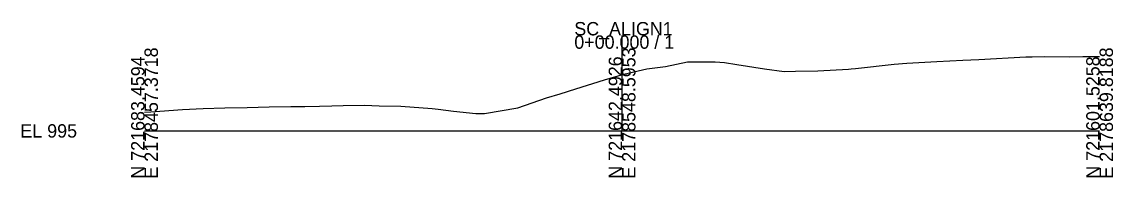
# Model space of a CAD drawing. Extents: x -2342 to 14913, y -10 to 5257.
# Drawn here: x -25.7 to 202.8, y -9.7 to 22.8 of the extents above; entities that cross this region are included whole.
import ezdxf

# ---------------------------------------------------------------- set-up
doc = ezdxf.new("R2010")
doc.units = 0
for name, color, linetype in [('Default', 7, 'Continuous'), ('GK_Cells', 7, 'Continuous'), ('SC_Scratch1', 7, 'Continuous'), ('XS_X_Ground_Line', 7, 'Continuous')]:
    doc.layers.add(name, color=color, linetype=linetype)

msp = doc.modelspace()

# ---------------------------------------------------------------- linework, layer by layer
at = {"layer": 'GK_Cells'}
for p, q in [((100, 0), (100, 20)), ((0, 0), (100, 0)), ((100, 0), (200, 0))]:
    msp.add_line(p, q, dxfattribs=at)
at = {"layer": 'SC_Scratch1'}
msp.add_lwpolyline([(0, 3.9), (1.29, 3.98), (7.94, 4.49), (12.26, 4.72), (16.82, 4.85), (21.48, 4.92), (26.12, 5.02), (30.63, 5.08), (33.56, 5.13), (36.67, 5.18), (39.22, 5.28), (41.63, 5.3), (46.04, 5.37), (49.13, 5.24), (53.67, 5.16), (60.2, 4.66), (61.47, 4.52), (64.72, 4.16), (69.38, 3.62), (71.21, 3.63), (78.15, 4.85), (84.21, 6.92), (87.06, 7.76), (90.29, 8.78), (96.3, 10.68), (100.4, 11.86), (105.2, 12.97), (109.11, 13.48), (113.68, 14.46), (119.49, 14.48), (121.44, 14.33), (124.03, 13.91), (129.8, 12.97), (133.95, 12.43), (136.35, 12.54), (140.96, 12.56), (147.44, 12.93), (147.97, 12.97), (148.87, 13.07), (156.96, 13.97), (159.6, 14.19), (165.93, 14.53), (171.37, 14.81), (174.71, 14.94), (184.56, 15.49), (185.9, 15.52), (188.54, 15.58), (193.64, 15.51), (196.5, 15.6), (200, 15.61)], dxfattribs=at)
at = {"layer": 'XS_X_Ground_Line'}
msp.add_lwpolyline([(0, 3.9), (1.29, 3.98), (7.94, 4.49), (12.26, 4.72), (16.82, 4.85), (21.48, 4.92), (26.12, 5.02), (30.63, 5.08), (33.56, 5.13), (36.67, 5.18), (39.22, 5.28), (41.63, 5.3), (46.04, 5.37), (49.13, 5.24), (53.67, 5.16), (60.2, 4.66), (61.47, 4.52), (64.72, 4.16), (69.38, 3.62), (71.21, 3.63), (78.15, 4.85), (84.21, 6.92), (87.06, 7.76), (90.29, 8.78), (96.3, 10.68), (100.4, 11.86), (105.2, 12.97), (109.11, 13.48), (113.68, 14.46), (119.49, 14.48), (121.44, 14.33), (124.03, 13.91), (129.8, 12.97), (133.95, 12.43), (136.35, 12.54), (140.96, 12.56), (147.44, 12.93), (147.97, 12.97), (148.87, 13.07), (156.96, 13.97), (159.6, 14.19), (165.93, 14.53), (171.37, 14.81), (174.71, 14.94), (184.56, 15.49), (185.9, 15.52), (188.54, 15.58), (193.64, 15.51), (196.5, 15.6), (200, 15.61)], dxfattribs=at)

# ---------------------------------------------------------------- texts
at = {"layer": 'Default'}
msp.add_text('-', height=0.0001, dxfattribs=at).set_placement((0, 0))
at = {"layer": 'GK_Cells'}
for s, p in [('SC_ALIGN1', (90, 20)), ('0+00.000 / 1', (90, 17.2)), ('EL 995', (-26, -1.4))]:
    msp.add_text(s, height=2.8, dxfattribs=at).set_placement(p)
for s, p in [('E 2178457.3718', (2.8, -10)), ('E 2178548.5953', (102.8, -10)), ('E 2178639.8188', (202.8, -10)), ('N 721683.4594', (0, -10)), ('N 721642.4926', (100, -10)), ('N 721601.5258', (200, -10))]:
    msp.add_text(s, height=2.8, rotation=90, dxfattribs=at).set_placement(p)
at = {"layer": 'SC_Scratch1'}
msp.add_text('X', height=0.0001, dxfattribs=at).set_placement((100, 11.74))

doc.saveas('drawing.dxf')
